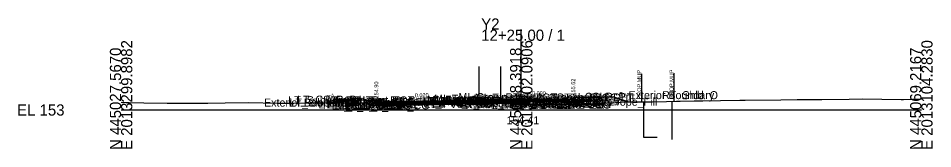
# Model space of a CAD drawing. Extents: x -26 to 203, y -10 to 6017.
# Drawn here: x -25.7 to 202.8, y 4490.3 to 4523 of the extents above; entities that cross this region are included whole.
import ezdxf

# ---------------------------------------------------------------- set-up
doc = ezdxf.new("R2010")
doc.units = 0
for name, color, linetype in [('Default', 7, 'Continuous'), ('Exist Cross Section Cell', 7, 'Continuous'), ('Exist XS Center Line Elevation Label', 7, 'Continuous'), ('Exist XS Ground Line', 7, 'Continuous'), ('Prop CMT Conc Surface', 7, 'Continuous'), ('Prop CMT Concrete Structures', 7, 'Continuous'), ('Prop CMT Pvmt Course 1', 7, 'Continuous'), ('Prop CMT Pvmt Course 1 CG', 7, 'Continuous'), ('Prop CMT Pvmt Course 1 Wedge', 7, 'Continuous'), ('Prop CMT Pvmt Course 2', 7, 'Continuous'), ('Prop CMT Pvmt Course 2 Wedge', 7, 'Continuous'), ('Prop CMT Pvmt Course 3', 7, 'Continuous'), ('Prop CMT Pvmt Course 3 Wedge', 7, 'Continuous'), ('Prop CMT Pvmt Surface', 7, 'Continuous'), ('Prop CMT Pvmt Wedge Surface 1', 7, 'Continuous'), ('Prop CMT Pvmt Wedge Surface 2', 7, 'Continuous'), ('Prop CMT Pvmt Wedge Surface 3', 7, 'Continuous'), ('Prop CMT Slope Grass', 7, 'Continuous'), ('Prop CMT Subgrade Earthwork', 7, 'Continuous'), ('Prop XS Earthwork Shape', 7, 'Continuous'), ('Prop XS Hydro Elevations', 7, 'Continuous'), ('Prop XS Label Text', 7, 'Continuous'), ('Prop XS SE Text', 7, 'Continuous'), ('Prop XS Side Slope Text', 7, 'Continuous'), ('Scratch_Level_0', 7, 'Continuous'), ('Scratch_Level_1', 7, 'Continuous'), ('Scratch_Level_3', 7, 'Continuous')]:
    doc.layers.add(name, color=color, linetype=linetype)

msp = doc.modelspace()

# ---------------------------------------------------------------- linework, layer by layer
at = {"layer": 'Exist Cross Section Cell'}
for p, q in [((100, 4500), (100, 4520.11)), ((0, 4500), (100, 4500)), ((100, 4500), (200, 4500))]:
    msp.add_line(p, q, dxfattribs=at)
at = {"layer": 'Exist XS Ground Line'}
msp.add_lwpolyline([(0, 4501.94), (1.26, 4501.88), (2.04, 4501.86), (5.71, 4501.8), (11.49, 4501.74), (13.05, 4501.74), (21.71, 4501.73), (26.04, 4501.78), (31.94, 4501.85), (39.03, 4501.69), (42.16, 4501.67), (52.02, 4501.86), (52.39, 4501.86), (53.73, 4501.86), (61.05, 4501.79), (62.61, 4501.77), (69.48, 4501.55), (73.66, 4501.57), (86.71, 4501.66), (93.53, 4501.7), (94.54, 4501.71), (95.7, 4501.72), (97.86, 4501.43), (100, 4501.41), (100.81, 4501.41), (107.88, 4501.36), (116.55, 4501.38), (118.36, 4501.35), (119.85, 4501.67), (120.94, 4501.73), (126.05, 4502.07), (129.28, 4502.07), (132.8, 4502.07), (143.25, 4502.29), (145.36, 4502.33), (149.78, 4502.38), (154.64, 4502.46), (155.96, 4502.47), (164.87, 4502.55), (168.95, 4502.61), (175.09, 4502.64), (181.94, 4502.69), (185.32, 4502.81), (194.93, 4502.64), (195.54, 4502.64), (197.81, 4502.7), (200, 4502.79)], dxfattribs=at)
at = {"layer": 'Prop CMT Conc Surface'}
for points in [[(59.29, 4502.49), (54.29, 4502.59)], [(63.79, 4501.9), (63.79, 4502.4), (63.29, 4502.4)], [(110.99, 4502.7), (112.99, 4502.62)], [(112.99, 4502.62), (112.99, 4503.12), (113.49, 4503.12)], [(65.79, 4502.02), (63.79, 4501.9)]]:
    msp.add_lwpolyline(points, dxfattribs=at)
at = {"layer": 'Prop CMT Concrete Structures'}
for p, q in [((89.51, 4502.66), (89.5, 4502.49)), ((90.26, 4502.91), (89.51, 4502.66)), ((94.15, 4503.12), (90.26, 4502.91)), ((94.9, 4502.87), (94.15, 4503.12)), ((94.91, 4502.7), (94.9, 4502.87))]:
    msp.add_line(p, q, dxfattribs=at)
for points in [[(54.29, 4502.26), (54.29, 4502.59)], [(54.29, 4502.59), (59.29, 4502.49)], [(59.29, 4502.16), (54.29, 4502.26)], [(59.29, 4502.49), (59.29, 4502.16)], [(65.79, 4502.02), (63.79, 4501.9), (63.79, 4502.4), (63.29, 4502.4)], [(63.29, 4502.4), (63.29, 4501.39), (65.79, 4501.44)], [(89.5, 4502.49), (94.91, 4502.7)], [(110.99, 4502.7), (112.99, 4502.62), (112.99, 4503.12), (113.49, 4503.12)], [(113.49, 4503.12), (113.49, 4502.12), (110.99, 4502.12)], [(110.99, 4502.12), (110.99, 4502.7)], [(65.79, 4501.44), (65.79, 4502.02)]]:
    msp.add_lwpolyline(points, dxfattribs=at)
at = {"layer": 'Prop CMT Pvmt Course 1'}
for points in [[(89.5, 4502.49), (65.79, 4502.02)], [(65.79, 4501.77), (89.5, 4502.24)], [(89.5, 4502.24), (89.5, 4502.49)], [(89.5, 4502.24), (89.5, 4502.49)], [(94.91, 4502.45), (89.5, 4502.24)], [(89.5, 4502.37), (89.5, 4502.24), (89.5, 4502.24)], [(94.91, 4502.7), (110.99, 4502.7)], [(94.91, 4502.45), (94.91, 4502.7)], [(94.91, 4502.7), (94.91, 4502.45)], [(94.91, 4502.58), (94.91, 4502.45), (94.91, 4502.45)], [(97.9, 4502.45), (94.91, 4502.45)], [(97.9, 4502.45), (97.9, 4502.7)], [(97.9, 4502.7), (97.9, 4502.45)], [(109.99, 4502.58), (97.9, 4502.58)], [(97.9, 4502.58), (97.9, 4502.45), (97.9, 4502.45)], [(109.99, 4502.45), (109.99, 4502.58)], [(110.99, 4502.45), (109.99, 4502.45)], [(110.99, 4502.7), (110.99, 4502.45)], [(65.79, 4502.02), (65.79, 4501.77)]]:
    msp.add_lwpolyline(points, dxfattribs=at)
at = {"layer": 'Prop CMT Pvmt Course 1 CG'}
for points in [[(110.99, 4502.12), (113.99, 4502.12), (114.32, 4501.79)], [(110.99, 4501.87), (110.99, 4502.12)], [(65.79, 4501.44), (62.79, 4501.38), (62.45, 4501.04)], [(62.45, 4501.04), (65.79, 4501.1)], [(65.79, 4501.19), (65.79, 4501.44)], [(114.32, 4501.79), (110.99, 4501.79)]]:
    msp.add_lwpolyline(points, dxfattribs=at)
at = {"layer": 'Prop CMT Pvmt Course 1 Wedge'}
for points in [[(94.91, 4502.45), (94.91, 4502.58)], [(97.9, 4502.58), (100.81, 4502.58), (107.88, 4502.58), (109.99, 4502.58)], [(97.9, 4502.45), (97.9, 4502.58)], [(109.99, 4502.45), (107.88, 4502.45), (100.81, 4502.45), (97.9, 4502.45)], [(109.99, 4502.58), (109.99, 4502.45)]]:
    msp.add_lwpolyline(points, dxfattribs=at)
at = {"layer": 'Prop CMT Pvmt Course 2'}
for points in [[(89.5, 4502.24), (65.79, 4501.77)], [(89.5, 4502.24), (94.91, 4502.45)], [(89.5, 4501.91), (89.5, 4502.24)], [(94.91, 4502.12), (89.5, 4501.91)], [(94.91, 4502.45), (94.91, 4502.12)], [(94.91, 4502.45), (97.9, 4502.45)], [(97.9, 4502.12), (94.91, 4502.12)], [(97.9, 4502.45), (97.9, 4502.12)], [(109.99, 4502.12), (109.99, 4502.45)], [(109.99, 4502.45), (110.99, 4502.45)], [(110.99, 4502.12), (109.99, 4502.12)], [(110.99, 4502.45), (110.99, 4502.12)], [(65.79, 4501.44), (89.5, 4501.91)], [(65.79, 4501.77), (65.79, 4501.44)]]:
    msp.add_lwpolyline(points, dxfattribs=at)
at = {"layer": 'Prop CMT Pvmt Course 2 Wedge'}
for points in [[(94.91, 4502.12), (94.91, 4502.45)], [(97.9, 4502.45), (100.81, 4502.45), (107.88, 4502.45), (109.99, 4502.45)], [(97.9, 4502.12), (97.9, 4502.45)], [(109.99, 4502.12), (107.88, 4502.12), (100.81, 4502.12), (97.9, 4502.12)], [(109.99, 4502.45), (109.99, 4502.12)]]:
    msp.add_lwpolyline(points, dxfattribs=at)
at = {"layer": 'Prop CMT Pvmt Course 3'}
for points in [[(89.5, 4501.91), (94.91, 4502.12)], [(94.91, 4502.12), (94.91, 4501.79)], [(94.91, 4502.12), (97.9, 4502.12)], [(97.9, 4502.12), (97.9, 4501.79)], [(109.99, 4502.12), (110.99, 4502.12)], [(109.99, 4501.79), (109.99, 4502.12)], [(110.99, 4502.12), (110.99, 4501.79)], [(89.5, 4501.91), (65.79, 4501.44)], [(65.79, 4501.1), (89.5, 4501.58)], [(65.79, 4501.44), (65.79, 4501.1)], [(89.5, 4501.58), (89.5, 4501.91)], [(94.91, 4501.79), (89.5, 4501.58)], [(97.9, 4501.79), (94.91, 4501.79)], [(110.99, 4501.79), (109.99, 4501.79)]]:
    msp.add_lwpolyline(points, dxfattribs=at)
at = {"layer": 'Prop CMT Pvmt Course 3 Wedge'}
for points in [[(97.9, 4502.12), (100.81, 4502.12), (107.88, 4502.12), (109.99, 4502.12)], [(97.9, 4501.43), (97.9, 4502.12)], [(109.99, 4502.12), (109.99, 4501.37)], [(109.99, 4501.37), (107.88, 4501.36), (100.81, 4501.41), (97.9, 4501.43)]]:
    msp.add_lwpolyline(points, dxfattribs=at)
at = {"layer": 'Prop CMT Pvmt Surface'}
for points in [[(89.5, 4502.49), (65.79, 4502.02)], [(89.5, 4502.49), (94.91, 4502.7)], [(94.91, 4502.7), (110.99, 4502.7)]]:
    msp.add_lwpolyline(points, dxfattribs=at)
at = {"layer": 'Prop CMT Pvmt Wedge Surface 1'}
for points in [[(94.91, 4502.7), (94.91, 4502.45), (94.91, 4502.45), (94.91, 4502.58)], [(97.9, 4502.7), (97.9, 4502.45), (97.9, 4502.45), (97.9, 4502.58)], [(97.9, 4502.58), (109.99, 4502.58)], [(109.99, 4502.58), (109.99, 4502.45)], [(109.99, 4502.45), (110.99, 4502.45)], [(110.99, 4502.45), (110.99, 4502.7)]]:
    msp.add_lwpolyline(points, dxfattribs=at)
at = {"layer": 'Prop CMT Pvmt Wedge Surface 2'}
for points in [[(94.91, 4502.7), (94.91, 4502.45)], [(97.9, 4502.7), (97.9, 4502.45)], [(97.9, 4502.45), (110.99, 4502.45)], [(110.99, 4502.45), (110.99, 4502.7)]]:
    msp.add_lwpolyline(points, dxfattribs=at)
at = {"layer": 'Prop CMT Pvmt Wedge Surface 3'}
for points in [[(94.91, 4502.7), (94.91, 4502.12)], [(97.9, 4502.7), (97.9, 4502.12)], [(97.9, 4502.12), (110.99, 4502.12)], [(110.99, 4502.12), (110.99, 4502.7)]]:
    msp.add_lwpolyline(points, dxfattribs=at)
at = {"layer": 'Prop CMT Slope Grass'}
for points in [[(63.29, 4502.4), (53.79, 4502.59), (51.58, 4501.85)], [(113.49, 4503.12), (122.99, 4503.31)], [(122.99, 4503.31), (126.73, 4502.07)]]:
    msp.add_lwpolyline(points, dxfattribs=at)
at = {"layer": 'Prop CMT Subgrade Earthwork'}
msp.add_line((97.9, 4501.79), (97.9, 4501.43), dxfattribs=at)
for points in [[(65.79, 4501.1), (62.45, 4501.04), (61.04, 4502.44)], [(110.99, 4501.79), (114.32, 4501.79), (115.7, 4503.17)], [(89.5, 4501.58), (65.79, 4501.1)], [(89.5, 4501.58), (94.91, 4501.79)], [(94.91, 4501.79), (97.9, 4501.79)], [(109.99, 4501.79), (109.97, 4501.37)], [(109.99, 4501.79), (110.99, 4501.79)]]:
    msp.add_lwpolyline(points, dxfattribs=at)
at = {"layer": 'Prop XS Earthwork Shape'}
for points in [[(61.71, 4501.78), (61.04, 4502.44), (53.79, 4502.59), (51.58, 4501.85), (52.02, 4501.86), (52.39, 4501.86), (53.73, 4501.86), (61.05, 4501.79)], [(61.71, 4501.78), (61.04, 4502.44), (53.79, 4502.59), (51.58, 4501.85), (52.02, 4501.86), (52.39, 4501.86), (53.73, 4501.86), (61.05, 4501.79)], [(61.05, 4501.79), (61.71, 4501.78), (61.04, 4502.44), (53.79, 4502.59), (51.58, 4501.85), (52.02, 4501.86), (52.39, 4501.86), (53.73, 4501.86)], [(61.05, 4501.79), (61.71, 4501.78), (61.04, 4502.44), (53.79, 4502.59), (51.58, 4501.85), (52.02, 4501.86), (52.39, 4501.86), (53.73, 4501.86)], [(109.97, 4501.37), (116.55, 4501.38), (118.36, 4501.35), (119.85, 4501.67), (120.94, 4501.73), (126.05, 4502.07), (126.73, 4502.07), (122.99, 4503.31), (115.7, 4503.17), (114.32, 4501.79), (110.99, 4501.79), (109.99, 4501.79)], [(109.97, 4501.37), (116.55, 4501.38), (118.36, 4501.35), (119.85, 4501.67), (120.94, 4501.73), (126.05, 4502.07), (126.73, 4502.07), (122.99, 4503.31), (115.7, 4503.17), (114.32, 4501.79), (110.99, 4501.79), (109.99, 4501.79)], [(109.97, 4501.37), (116.55, 4501.38), (118.36, 4501.35), (119.85, 4501.67), (120.94, 4501.73), (126.05, 4502.07), (126.73, 4502.07), (122.99, 4503.31), (115.7, 4503.17), (114.32, 4501.79), (110.99, 4501.79), (109.99, 4501.79)], [(109.97, 4501.37), (116.55, 4501.38), (118.36, 4501.35), (119.85, 4501.67), (120.94, 4501.73), (126.05, 4502.07), (126.73, 4502.07), (122.99, 4503.31), (115.7, 4503.17), (114.32, 4501.79), (110.99, 4501.79), (109.99, 4501.79)], [(62.45, 4501.04), (61.71, 4501.78), (62.61, 4501.77), (63.29, 4501.75), (63.29, 4501.39), (65.79, 4501.44), (65.79, 4501.67), (69.48, 4501.55), (73.66, 4501.57), (86.71, 4501.66), (93.53, 4501.7), (94.39, 4501.71), (84.59, 4501.48), (65.79, 4501.1)], [(63.29, 4501.39), (65.79, 4501.44), (65.79, 4501.67), (69.48, 4501.55), (73.66, 4501.57), (86.71, 4501.66), (93.53, 4501.7), (94.39, 4501.71), (84.59, 4501.48), (65.79, 4501.1), (62.45, 4501.04), (61.71, 4501.78), (62.61, 4501.77), (63.29, 4501.75)], [(62.45, 4501.04), (61.71, 4501.78), (62.61, 4501.77), (63.29, 4501.75), (63.29, 4501.39), (65.79, 4501.44), (65.79, 4501.67), (69.48, 4501.55), (73.66, 4501.57), (86.71, 4501.66), (93.53, 4501.7), (94.39, 4501.71), (84.59, 4501.48), (65.79, 4501.1)], [(62.45, 4501.04), (61.71, 4501.78), (62.61, 4501.77), (63.29, 4501.75), (63.29, 4501.39), (65.79, 4501.44), (65.79, 4501.67), (69.48, 4501.55), (73.66, 4501.57), (86.71, 4501.66), (93.53, 4501.7), (94.39, 4501.71), (84.59, 4501.48), (65.79, 4501.1)], [(63.29, 4501.39), (65.79, 4501.44), (65.79, 4501.67), (63.29, 4501.75)], [(63.29, 4501.39), (65.79, 4501.44), (65.79, 4501.67), (63.29, 4501.75)], [(63.29, 4501.39), (65.79, 4501.44), (65.79, 4501.67), (63.29, 4501.75)], [(63.29, 4501.39), (65.79, 4501.44), (65.79, 4501.67), (63.29, 4501.75)], [(94.39, 4501.71), (97.9, 4501.79), (97.9, 4501.43), (97.86, 4501.43), (95.7, 4501.72), (94.54, 4501.71)], [(94.39, 4501.71), (97.9, 4501.79), (97.9, 4501.43), (97.86, 4501.43), (95.7, 4501.72), (94.54, 4501.71)], [(94.39, 4501.71), (97.9, 4501.79), (97.9, 4501.43), (97.86, 4501.43), (95.7, 4501.72), (94.54, 4501.71)], [(94.39, 4501.71), (97.9, 4501.79), (97.9, 4501.43), (97.86, 4501.43), (95.7, 4501.72), (94.54, 4501.71)]]:
    msp.add_lwpolyline(points, close=True, dxfattribs=at)
at = {"layer": 'Prop XS Label Text'}
for p, q in [((130.1, 4509.07), (130.1, 4502.07)), ((138.18, 4509.18), (138.18, 4502.18))]:
    msp.add_line(p, q, dxfattribs=at)
at = {"layer": 'Scratch_Level_1'}
for p, q in [((137.68, 4502.17), (137.68, 4492.63)), ((130.6, 4502.07), (130.6, 4493.19)), ((130.6, 4493.19), (134.01, 4493.19))]:
    msp.add_line(p, q, dxfattribs=at)
at = {"layer": 'Scratch_Level_3'}
for p, q in [((89.5, 4502.49), (89.5, 4510.88)), ((94.91, 4502.7), (94.91, 4510.88))]:
    msp.add_line(p, q, dxfattribs=at)

# ---------------------------------------------------------------- texts
at = {"layer": 'Default'}
msp.add_text('-', height=0.0001, dxfattribs=at).set_placement((0, 4500))
at = {"layer": 'Exist Cross Section Cell'}
for s, p in [('Y2', (90, 4520.11)), ('12+25.00 / 1', (90, 4517.31)), ('EL 153', (-26, 4498.6))]:
    msp.add_text(s, height=2.8, dxfattribs=at).set_placement(p)
for s, p in [('E 2013299.8982', (2.8, 4490)), ('E 2013202.0906', (102.8, 4490)), ('E 2013104.2830', (202.8, 4490)), ('N 445027.5670', (0, 4490)), ('N 445048.3918', (100, 4490)), ('N 445069.2167', (200, 4490))]:
    msp.add_text(s, height=2.8, rotation=90, dxfattribs=at).set_placement(p)
at = {"layer": 'Exist XS Center Line Elevation Label'}
msp.add_text('154.41', height=2, dxfattribs=at).set_placement((96.32, 4496.41))
at = {"layer": 'Prop XS Hydro Elevations'}
for s, p in [('154.90', (64.29, 4502.9)), ('155.62', (113.49, 4503.62))]:
    msp.add_text(s, height=1, rotation=90, dxfattribs=at).set_placement(p)
at = {"layer": 'Prop XS Label Text'}
for p in [(130, 4502.64), (138.08, 4502.75)]:
    msp.add_text('PROP.MUP', height=1, rotation=90, dxfattribs=at).set_placement(p)
at = {"layer": 'Prop XS SE Text'}
msp.add_text('0.000', height=1, dxfattribs=at).set_placement((102.69, 4503.7))
msp.add_text('0.020', height=1, rotation=1.1458, dxfattribs=at).set_placement((73.42, 4503.17))
at = {"layer": 'Prop XS Side Slope Text'}
for rotation, p in [(341.5651, (124.35, 4503.65)), (18.4349, (51.69, 4502.68))]:
    msp.add_text('3:1', height=1, rotation=rotation, dxfattribs=at).set_placement(p)
at = {"layer": 'Scratch_Level_0'}
for s, p in [('Exterior Boundary', (126.82, 4502.71)), ('RT_Shld_O', (135.21, 4502.71)), ('Exterior Boundary', (35.72, 4500.85)), ('LT_Sub_Trench_Out_DLT', (41.78, 4501.44)), ('LT_Slope_Fill', (42.1, 4500.85)), ('LT_CSLP_Pnt', (43.96, 4501.59)), ('LT_CG1_Shelf_Out', (49.34, 4500.38)), ('LT_CG_Top_Face', (51.05, 4501.4)), ('LT_CG_Top_BOC', (51.57, 4501.4)), ('LT_CG_Bot_BOC', (51.61, 4500.39)), ('LT_CG_Top_Gut', (52.03, 4500.9)), ('LT_Sub_OEOP', (52.65, 4500.12)), ('LT_Sub_OEOT_CG', (53.16, 4500.19)), ('LT_CG_Bot_IE', (55.7, 4500.44)), ('LT_Sub_OEOT', (55.87, 4500.1)), ('LT_PV2_OEOT', (55.96, 4500.77)), ('LT_PV3_OEOT', (55.96, 4500.44)), ('LT_PV1_OEOT', (56.53, 4501.02)), ('LT_PV2_IEEOP', (74.54, 4501.15)), ('LT_PV1_IEEOP', (75.11, 4501.27)), ('LT_PV2_PGL1', (75.47, 4501.15)), ('LT_PV3_PGL1', (75.47, 4500.81)), ('LT_PV2_PGL', (75.8, 4501.15)), ('LT_PV4_PGL', (75.8, 4500.48)), ('LT_PV1_PGL', (76.37, 4501.4)), ('MI_Face In', (76.49, 4501.56)), ('MI_Top In', (78.2, 4501.81)), ('MI_Crown', (84.31, 4502.24)), ('LT_Sub_OEEOP', (84.91, 4500.7)), ('LT_PV2_OEEOP', (85, 4501.37)), ('LT_PV3_OEEOP', (85, 4501.03)), ('LT_PV1_OEEOP', (85.57, 4501.49)), ('RT_PV_IEEOP_EG', (86.04, 4500.43)), ('RT_PV2_IEEOP', (87.8, 4501.45)), ('RT_PV3_IEEOP', (87.8, 4501.12)), ('MI_Face Out', (88.15, 4501.87)), ('MI_Top Out', (88.36, 4502.12)), ('RT_PV1_IEEOP', (88.37, 4501.58)), ('RT_PV2_PGL1', (88.73, 4501.45)), ('RT_PV3_PGL1', (88.73, 4501.12)), ('RT_PV2_PGL', (89.06, 4501.45)), ('RT_PV3_PGL', (89.06, 4501.12)), ('RT_PV4_PGL', (89.06, 4500.79)), ('MI_Bot Out', (89.16, 4501.7)), ('RT_PV1_PGL', (89.63, 4501.7)), ('RT_PV_EG_TestPt', (90.3, 4500.39)), ('RT_PV_Sub_Tie_Out', (94.87, 4500.37)), ('RT_Sub_Trench_Out_DLT', (96.05, 4502.16)), ('RT_PV_OEEOP_EG', (97.48, 4500.37)), ('RT_Sub_OEOT_CG', (98.31, 4500.87)), ('RT_Sub_OEEOP', (99.15, 4500.79)), ('RT_PV2_OEEOP', (99.25, 4501.45)), ('RT_PV3_OEEOP', (99.25, 4501.12)), ('RT_PV1_OEEOP', (99.81, 4501.58)), ('RT_CG_Top_Face', (100.2, 4502.12)), ('RT_CG1_Shelf_Out', (100.49, 4501.12)), ('RT_CG_Bot_IE', (100.85, 4501.12)), ('RT_Sub_OEOT', (101.02, 4500.79)), ('RT_PV2_OEOT', (101.11, 4501.45)), ('RT_PV3_OEOT', (101.11, 4501.12)), ('RT_CG_Top_Gut', (101.18, 4501.62)), ('RT_PV1_OEOT', (101.68, 4501.7)), ('RT_CG_Top_BOC', (101.73, 4502.12)), ('RT_CG_Bot_BOC', (101.76, 4501.12)), ('RT_Sub_OEOP', (104.3, 4500.87)), ('CSLP_Pnt', (115.86, 4502.31)), ('RT_Slope_Fill', (117.21, 4501.07))]:
    msp.add_text(s, height=2, dxfattribs=at).set_placement(p)

doc.saveas('drawing.dxf')
